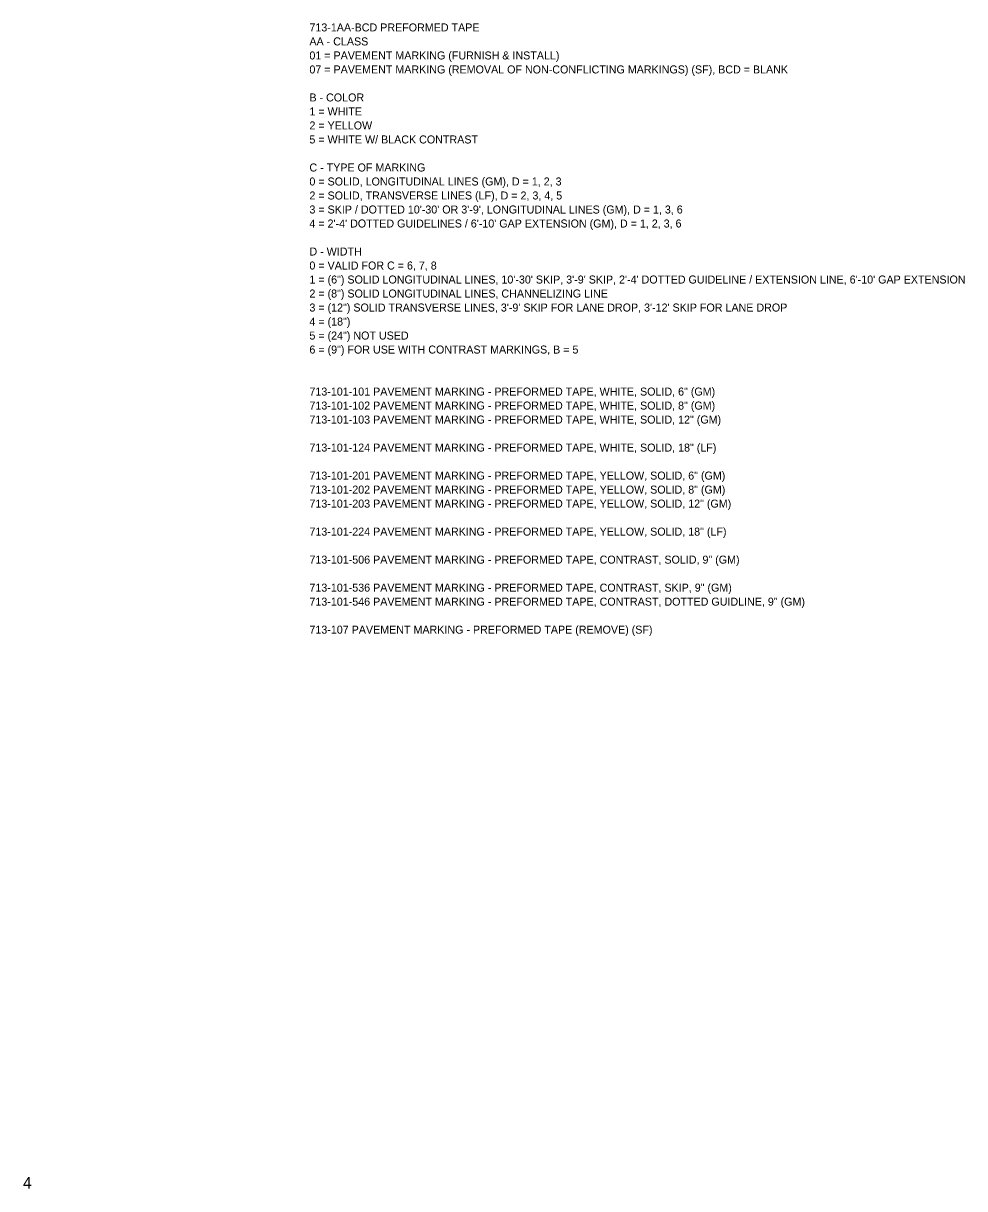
# Model space of a CAD drawing. Extents: x 2479959 to 2482299, y 3677554 to 3678604.
# Drawn here: x 2481505 to 2482299, y 3677579 to 3678562 of the extents above; entities that cross this region are included whole.
import ezdxf

# ---------------------------------------------------------------- set-up
doc = ezdxf.new("R2010")
doc.units = 0
doc.layers.add('TextLabel', color=7, linetype='Continuous')
doc.layers.add('TextShtNo', color=7, linetype='Continuous')

msp = doc.modelspace()

# ---------------------------------------------------------------- texts
at = {"layer": 'TextLabel'}
for s, p in [('713-1AA-BCD PREFORMED TAPE', (2481746.36, 3678555.43)), ('AA - CLASS', (2481746.36, 3678543.61)), ('01 = PAVEMENT MARKING (FURNISH & INSTALL)', (2481746.36, 3678531.8)), ('07 = PAVEMENT MARKING (REMOVAL OF NON-CONFLICTING MARKINGS) (SF), BCD = BLANK', (2481746.36, 3678519.99)), ('B - COLOR', (2481746.36, 3678496.36)), ('1 = WHITE', (2481746.36, 3678484.55)), ('2 = YELLOW', (2481746.36, 3678472.74)), ('5 = WHITE W/ BLACK CONTRAST', (2481746.36, 3678460.93)), ('C - TYPE OF MARKING', (2481746.36, 3678437.3)), ('0 = SOLID, LONGITUDINAL LINES (GM), D = 1, 2, 3', (2481746.36, 3678425.49)), ('2 = SOLID, TRANSVERSE LINES (LF), D = 2, 3, 4, 5', (2481746.36, 3678413.68)), ("3 = SKIP / DOTTED 10'-30' OR 3'-9', LONGITUDINAL LINES (GM), D = 1, 3, 6", (2481746.36, 3678401.86)), ("4 = 2'-4' DOTTED GUIDELINES / 6'-10' GAP EXTENSION (GM), D = 1, 2, 3, 6", (2481746.36, 3678390.05)), ('D - WIDTH', (2481746.36, 3678366.43)), ('0 = VALID FOR C = 6, 7, 8', (2481746.36, 3678354.61)), ('1 = (6") SOLID LONGITUDINAL LINES, 10\'-30\' SKIP, 3\'-9\' SKIP, 2\'-4\' DOTTED GUIDELINE / EXTENSION LINE, 6\'-10\' GAP EXTENSION', (2481746.36, 3678342.8)), ('2 = (8") SOLID LONGITUDINAL LINES, CHANNELIZING LINE', (2481746.36, 3678330.99)), ('3 = (12") SOLID TRANSVERSE LINES, 3\'-9\' SKIP FOR LANE DROP, 3\'-12\' SKIP FOR LANE DROP', (2481746.36, 3678319.18)), ('4 = (18")', (2481746.36, 3678307.36)), ('5 = (24") NOT USED', (2481746.36, 3678295.55)), ('6 = (9") FOR USE WITH CONTRAST MARKINGS, B = 5', (2481746.36, 3678283.74)), ('713-101-101 PAVEMENT MARKING - PREFORMED TAPE, WHITE, SOLID, 6" (GM)', (2481746.36, 3678248.3)), ('713-101-102 PAVEMENT MARKING - PREFORMED TAPE, WHITE, SOLID, 8" (GM)', (2481746.36, 3678236.49)), ('713-101-103 PAVEMENT MARKING - PREFORMED TAPE, WHITE, SOLID, 12" (GM)', (2481746.36, 3678224.68)), ('713-101-124 PAVEMENT MARKING - PREFORMED TAPE, WHITE, SOLID, 18" (LF)', (2481746.36, 3678201.05)), ('713-101-201 PAVEMENT MARKING - PREFORMED TAPE, YELLOW, SOLID, 6" (GM)', (2481746.36, 3678177.43)), ('713-101-202 PAVEMENT MARKING - PREFORMED TAPE, YELLOW, SOLID, 8" (GM)', (2481746.36, 3678165.61)), ('713-101-203 PAVEMENT MARKING - PREFORMED TAPE, YELLOW, SOLID, 12" (GM)', (2481746.36, 3678153.8)), ('713-101-224 PAVEMENT MARKING - PREFORMED TAPE, YELLOW, SOLID, 18" (LF)', (2481746.36, 3678130.18)), ('713-101-506 PAVEMENT MARKING - PREFORMED TAPE, CONTRAST, SOLID, 9" (GM)', (2481746.36, 3678106.55)), ('713-101-536 PAVEMENT MARKING - PREFORMED TAPE, CONTRAST, SKIP, 9" (GM)', (2481746.36, 3678082.93)), ('713-101-546 PAVEMENT MARKING - PREFORMED TAPE, CONTRAST, DOTTED GUIDLINE, 9" (GM)', (2481746.36, 3678071.11)), ('713-107 PAVEMENT MARKING - PREFORMED TAPE (REMOVE) (SF)', (2481746.36, 3678047.49))]:
    msp.add_text(s, height=6.75, dxfattribs=at).set_placement(p)
at = {"layer": 'TextShtNo'}
msp.add_text('  4   ', height=10, rotation=360, dxfattribs=at).set_placement((2481497.27, 3677579.35))

doc.saveas('drawing.dxf')
